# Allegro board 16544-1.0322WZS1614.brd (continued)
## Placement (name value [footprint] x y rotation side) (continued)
C436  SC10U25V5KX-DL-GP  [C805H58]  223.55 64.69 0 top
C440  SC1U10V2KX-L1-GP  [C402H22]  129.79 152.3 270 top
C450  SC10U6D3V3MX-DL-GP  [C603H36]  130.18 206.76 270 top
C451  SCD1U25V2KX-1-DL-GP  [C402H22]  129.03 205.1 180 top
C453  SC4D7U10V3KX-GP  [C603H36]  137.29 197.99 90 top
C454  SC22U6D3V5MX-2DLGP  [C805H54]  133.22 199.64 270 top
C455  SC22U6D3V5MX-2DLGP  [C805H54]  137.54 199.64 90 top
C456  SCD1U50V3KX-DL-GP  [C603H35]  22.87 117.21 0 top
C457  SCD1U25V2KX-1-DL-GP  [C402H22]  21.75 117.33 0 top
C458  SCD1U50V3KX-DL-GP  [C603H35]  33.73 112.93 270 bottom
C459  SC1U50V3KX-1-GP  [C603H36]  25.29 124.53 270 bottom
C460  SC1U6D3V2KX-GP  [C402H22]  209.37 150.27 90 top
C461  SC1U10V2KX-1DLGP  [C402H22]  207.21 143.9 90 top
C462  SCD1U25V2KX-1-DL-GP  [C402H22]  215.77 135.76 90 top
C463  SC1U6D3V2KX-GP  [C402H22]  218.67 136.04 270 top
C464  SC1U6D3V2KX-GP  [C402H22]  228.6 148.59 180 top
C466  SC1U10V2KX-1DLGP  [C402H22]  21.56 137.59 90 bottom
C467  SC1U50V3KX-1-GP  [C603H36]  20.93 139.57 180 bottom
C468  SC10U25V5KX-DL-GP  [C805H58]  88.01 24.43 90 top
C469  SC1U50V3KX-1-GP  [C603H36]  87.63 27.36 90 top
C470  SC10U6D3V3MX-DL-GP  [C603H36]  87.63 26.09 90 top
C471  SCD01U50V2KX-1DLGP  [C402H22]  100.08 82.37 270 top
C472  SCD01U50V2KX-1DLGP  [C402H22]  100.08 83.26 270 top
C473  SCD01U50V2KX-1DLGP  [C402H22]  96.47 86.64 270 top
C474  SCD01U50V2KX-1DLGP  [C402H22]  96.47 87.53 270 top
C475  SC10U25V5KX-DL-GP  [C805H58]  188.98 36.63 270 top
C476  SCD1U25V2KX-1-DL-GP  [C402H22]  189.15 38.05 270 top
C477  SCD1U25V2KX-1-DL-GP  [C402H22]  193.85 62.28 90 top
C478  SCD1U25V2KX-1-DL-GP  [C402H22]  193.85 63.17 90 top
C493  SC10P50V2JN-4DLGP  [C402H22]  184.51 8.46 270 top
C494  SC10P50V2JN-4DLGP  [C402H22]  186.66 8.46 90 top
C495  SCD1U25V2KX-1-DL-GP  [C402H22]  107.09 110.72 270 top
C496  SCD1U25V2KX-1-DL-GP  [C402H22]  107.09 109.83 270 top
C497  SCD1U25V2KX-1-DL-GP  [C402H22]  113.87 90.3 0 top
C498  SC1U10V2KX-1DLGP  [C402H22]  114.83 90.3 0 top
C499  SCD1U25V2KX-1-DL-GP  [C402H22]  97.43 91.59 270 top
C500  SC10U25V5KX-DL-GP  [C805H58]  97.61 90.17 270 top
C501  SCD1U25V2KX-1-DL-GP  [C402H22]  112.75 109.25 270 top
C502  SCD1U25V2KX-1-DL-GP  [C402H22]  112.75 108.36 270 top
C503  SCD1U25V2KX-1-DL-GP  [C402H22]  109.88 106.5 270 top
C504  SCD1U25V2KX-1-DL-GP  [C402H22]  109.88 105.61 270 top
C507  SC1KP50V2KX-1DLGP  [C402H22]  110.11 87.66 90 top
C508  SCD1U25V2KX-1-DL-GP  [C402H22]  103.89 91.16 90 top
C509  SC10U25V5KX-DL-GP  [C805H58]  116.41 90.25 0 top
C510  SCD01U50V2KX-1DLGP  [C402H22]  122.58 98.96 270 bottom
C511  SCD1U25V2KX-1-DL-GP  [C402H22]  122.56 99.87 270 bottom
C512  SC10U6D3V3MX-DL-GP  [C603H36]  122.94 97.92 270 bottom
C513  SCD1U25V2KX-1-DL-GP  [C402H22]  120.68 90.7 180 top
C514  SCD1U25V2KX-1-DL-GP  [C402H22]  119.79 90.7 180 top
C518  SCD1U25V2KX-1-DL-GP  [C402H22]  12.62 136.73 180 top
C521  SCD22U10V2KX-2-GP  [C402H22]  123.85 189.39 270 top
C522  SCD22U10V2KX-2-GP  [C402H22]  123.88 187.05 270 top
C523  SCD22U10V2KX-2-GP  [C402H22]  118.57 176.18 270 bottom
C524  SCD22U10V2KX-2-GP  [C402H22]  123.88 186.14 270 top
C525  SCD22U10V2KX-2-GP  [C402H22]  118.47 183.98 270 top
C526  SCD22U10V2KX-2-GP  [C402H22]  118.47 183.06 270 top
C527  SCD22U10V2KX-2-GP  [C402H22]  123.88 184.92 270 top
C528  SCD22U10V2KX-2-GP  [C402H22]  118.57 179.51 270 bottom
C529  SCD22U10V2KX-2-GP  [C402H22]  118.52 180.85 270 top
C530  SCD22U10V2KX-2-GP  [C402H22]  123.9 182.73 270 top
C531  SCD22U10V2KX-2-GP  [C402H22]  123.83 191.57 270 top
C532  SCD22U10V2KX-2-GP  [C402H22]  118.67 171.43 270 bottom
C533  SCD22U10V2KX-2-GP  [C402H22]  123.83 190.61 270 top
C534  SCD22U10V2KX-2-GP  [C402H22]  118.67 172.39 270 bottom
C535  SCD22U10V2KX-2-GP  [C402H22]  118.47 188.4 270 top
C536  SCD22U10V2KX-2-GP  [C402H22]  123.93 174.78 270 bottom
C537  SCD22U10V2KX-2-GP  [C402H22]  118.47 187.51 270 top
C538  SCD22U10V2KX-2-GP  [C402H22]  123.93 175.7 270 bottom
C539  SCD22U10V2KX-2-GP  [C402H22]  118.57 173.92 270 bottom
C540  SCD22U10V2KX-2-GP  [C402H22]  123.85 188.42 270 top
C541  SCD22U10V2KX-2-GP  [C402H22]  118.57 174.81 270 bottom
C542  SCD22U10V2KX-2-GP  [C402H22]  118.47 186.11 270 top
C543  SCD22U10V2KX-2-GP  [C402H22]  123.93 177.14 270 bottom
C544  SCD22U10V2KX-2-GP  [C402H22]  118.47 185.22 270 top
C545  SCD22U10V2KX-2-GP  [C402H22]  123.93 178.03 270 bottom
C546  SCD22U10V2KX-2-GP  [C402H22]  118.57 177.14 270 bottom
C547  SCD22U10V2KX-2-GP  [C402H22]  123.93 179.43 270 bottom
C548  SCD22U10V2KX-2-GP  [C402H22]  123.93 180.4 270 bottom
C549  SCD22U10V2KX-2-GP  [C402H22]  118.57 178.57 270 bottom
C550  SCD22U10V2KX-2-GP  [C402H22]  123.88 183.98 270 top
C551  SCD22U10V2KX-2-GP  [C402H22]  118.52 181.74 270 top
C552  SCD22U10V2KX-2-GP  [C402H22]  123.9 182.73 270 bottom
C553  SCD22U10V2KX-2-GP  [C402H22]  123.9 181.82 270 bottom
C554  SCD22U10V2KX-2-GP  [C402H22]  118.53 180.85 270 bottom
C555  SCD22U10V2KX-2-GP  [C402H22]  123.9 181.82 270 top
C556  SCD22U10V2KX-2-GP  [C402H22]  118.53 181.74 270 bottom
C557  SCD22U10V2KX-2-GP  [C402H22]  118.57 179.51 270 top
C558  SCD22U10V2KX-2-GP  [C402H22]  123.9 183.98 270 bottom
C559  SCD22U10V2KX-2-GP  [C402H22]  118.57 178.57 270 top
C560  SCD22U10V2KX-2-GP  [C402H22]  123.9 184.92 270 bottom
C561  SCD22U10V2KX-2-GP  [C402H22]  123.93 180.4 270 top
C562  SCD22U10V2KX-2-GP  [C402H22]  118.49 183.98 270 bottom
C563  SCD22U10V2KX-2-GP  [C402H22]  123.93 179.43 270 top
C564  SCD22U10V2KX-2-GP  [C402H22]  118.49 183.06 270 bottom
C565  SCD22U10V2KX-2-GP  [C402H22]  118.57 177.14 270 top
C566  SCD22U10V2KX-2-GP  [C402H22]  123.88 187.05 270 bottom
C567  SCD22U10V2KX-2-GP  [C402H22]  118.57 176.18 270 top
C568  SCD22U10V2KX-2-GP  [C402H22]  123.88 186.14 270 bottom
C569  SCD22U10V2KX-2-GP  [C402H22]  123.77 177.7 270 top
C570  SCD22U10V2KX-2-GP  [C402H22]  118.49 185.22 270 bottom
C571  SCD22U10V2KX-2-GP  [C402H22]  123.77 176.81 270 top
C572  SCD22U10V2KX-2-GP  [C402H22]  118.49 186.11 270 bottom
C573  SCD22U10V2KX-2-GP  [C402H22]  118.57 174.81 270 top
C574  SCD22U10V2KX-2-GP  [C402H22]  123.85 188.42 270 bottom
C575  SCD22U10V2KX-2-GP  [C402H22]  118.57 173.92 270 top
C576  SCD22U10V2KX-2-GP  [C402H22]  123.85 189.39 270 bottom
C577  SCD22U10V2KX-2-GP  [C402H22]  123.77 175.36 270 top
C578  SCD22U10V2KX-2-GP  [C402H22]  118.49 187.51 270 bottom
C579  SCD22U10V2KX-2-GP  [C402H22]  123.77 174.44 270 top
C580  SCD22U10V2KX-2-GP  [C402H22]  118.49 188.4 270 bottom
C581  SCD22U10V2KX-2-GP  [C402H22]  118.67 172.39 270 top
C582  SCD22U10V2KX-2-GP  [C402H22]  123.82 191.57 270 bottom
C583  SCD22U10V2KX-2-GP  [C402H22]  118.67 171.43 270 top
C584  SCD22U10V2KX-2-GP  [C402H22]  123.82 190.61 270 bottom
C592  SCD1U25V2KX-1-DL-GP  [C402H22]  108.23 205.58 90 top
C593  SC10U6D3V3MX-DL-GP  [C603H36]  75.54 165.89 270 bottom
C601  SC1U10V2KX-1DLGP  [C402H22]  73.35 171.85 0 bottom
C602  SC1U10V2KX-1DLGP  [C402H22]  74.74 171.73 270 bottom
C608  SC1U10V2KX-1DLGP  [C402H22]  83.01 174.8 180 bottom
C609  SC1U10V2KX-1DLGP  [C402H22]  82.42 177.01 90 bottom
C610  SC1U10V2KX-1DLGP  [C402H22]  83.08 178.84 0 bottom
C611  SC1U10V2KX-1DLGP  [C402H22]  81.05 172.03 90 bottom
C616  SCD1U25V2KX-1-DL-GP  [C402H22]  83.09 170.31 180 bottom
C617  SC1U10V2KX-1DLGP  [C402H22]  83.01 172.82 180 bottom
C618  SC1U10V2KX-1DLGP  [C402H22]  80.47 180.11 180 bottom
C619  SC10U6D3V3MX-DL-GP  [C603H36]  82.25 181 270 bottom
C622  SC10U6D3V3MX-DL-GP  [C603H36]  77.26 172.68 90 bottom
C630  SC1U10V2KX-1DLGP  [C402H22]  116.03 159.08 0 top
C631  SC1U10V2KX-1DLGP  [C402H22]  100.25 213.75 90 top
C632  SC1U10V2KX-1DLGP  [C402H22]  100.66 213.77 90 bottom
C634  SC1U10V2KX-1DLGP  [C402H22]  75.58 169.04 0 bottom
C637  SCD1U25V2KX-1-DL-GP  [C402H22]  125.89 165.86 180 top
C638  SC10U6D3V3MX-DL-GP  [C603H36]  99.59 149.21 0 top
C639  SC2D2U10V3KX-1DLGP-U  [C603H36]  100.84 149.21 0 top
C640  SC15P50V2JN-DL-GP  [C402H22]  101.52 152.08 0 top
C641  SC15P50V2JN-DL-GP  [C402H22]  101.53 154.04 180 top
C653  SCD01U50V2KX-1DLGP  [C402H22]  118.92 125.2 90 top
C656  SC1U10V2KX-1DLGP  [C402H22]  65.06 175.57 0 bottom
C657  SC1U10V2KX-1DLGP  [C402H22]  65.94 175.58 0 bottom
C658  SC1U10V2KX-1DLGP  [C402H22]  68.12 185.54 90 bottom
C659  SC1U10V2KX-1DLGP  [C402H22]  68.11 176.01 90 bottom
C660  SC1U10V2KX-1DLGP  [C402H22]  77.99 148.4 90 bottom
C661  SC1U10V2KX-1DLGP  [C402H22]  78.02 149.29 90 bottom
C662  SC1U10V2KX-1DLGP  [C402H22]  78.02 150.16 90 bottom
C663  SC22U6D3V3MX-1-DL-GP  [C603H40]  72.03 180.1 90 bottom
C664  SC22U6D3V3MX-1-DL-GP  [C603H40]  72.03 181.37 90 bottom
C665  SC22U6D3V3MX-1-DL-GP  [C603H40]  72.03 182.64 90 bottom
C666  SC22U6D3V3MX-1-DL-GP  [C603H40]  72.03 184.04 90 bottom
C667  SC22U6D3V3MX-1-DL-GP  [C603H40]  72.03 185.31 90 bottom
C668  SC1U10V2KX-1DLGP  [C402H22]  119.13 225.93 180 top
C669  SC1U10V2KX-1DLGP  [C402H22]  118.24 225.93 180 top
C670  SC1U10V2KX-1DLGP  [C402H22]  65.05 183.51 0 bottom
C671  SC1U10V2KX-1DLGP  [C402H22]  65.92 183.5 0 bottom
C672  SC1U10V2KX-1DLGP  [C402H22]  65.06 181.55 180 bottom
C673  SC1U10V2KX-1DLGP  [C402H22]  65.07 179.49 0 bottom
C674  SC1U10V2KX-1DLGP  [C402H22]  65.94 179.49 0 bottom
C675  SC1U10V2KX-1DLGP  [C402H22]  65.06 177.49 180 bottom
C676  SC22U6D3V3MX-1-DL-GP  [C603H40]  70.85 172.68 270 bottom
C677  SC22U6D3V3MX-1-DL-GP  [C603H40]  68.12 174.62 90 bottom
C678  SC22U6D3V3MX-1-DL-GP  [C603H40]  72.03 174.96 90 bottom
C679  SC22U6D3V3MX-1-DL-GP  [C603H40]  72.03 176.29 90 bottom
C680  SC22U6D3V3MX-1-DL-GP  [C603H40]  72.03 177.56 90 bottom
C681  SC22U6D3V3MX-1-DL-GP  [C603H40]  72.03 178.83 90 bottom
C682  SC22U6D3V3MX-1-DL-GP  [C603H40]  77.37 175.81 0 bottom
C683  SC1U10V2KX-1DLGP  [C402H22]  89.85 200.89 90 bottom
C684  SC1U10V2KX-1DLGP  [C402H22]  74.77 172.66 270 bottom
C685  SC1U10V2KX-1DLGP  [C402H22]  52.03 196.69 270 bottom
C686  SC1U10V2KX-1DLGP  [C402H22]  65.05 185.42 180 bottom
C687  SC22U6D3V3MX-1-DL-GP  [C603H40]  77.34 180.42 0 bottom
C688  SC1U10V2KX-1DLGP  [C402H22]  65.92 185.42 180 bottom
C689  SC1U10V2KX-1DLGP  [C402H22]  65.92 181.55 180 bottom
C690  SC1U10V2KX-1DLGP  [C402H22]  65.93 177.49 180 bottom
C691  SC1U10V2KX-1DLGP  [C402H22]  68.11 184.67 90 bottom
C692  SC1U10V2KX-1DLGP  [C402H22]  68.11 183.79 90 bottom
C693  SC22U6D3V3MX-1-DL-GP  [C603H40]  75.43 176.17 0 bottom
C694  SC22U6D3V3MX-1-DL-GP  [C603H40]  75.46 182.52 0 bottom
C695  SC22U6D3V3MX-1-DL-GP  [C603H40]  75.47 185.21 0 bottom
C696  SC1U10V2KX-1DLGP  [C402H22]  61.06 174.05 180 bottom
C697  SC1U10V2KX-1DLGP  [C402H22]  53.54 193.23 180 bottom
C698  SC1U10V2KX-1DLGP  [C402H22]  58.47 192.06 180 bottom
C699  SC1U10V2KX-1DLGP  [C402H22]  54.04 197.51 90 bottom
C700  SC1U10V2KX-1DLGP  [C402H22]  66.12 172.46 90 bottom
C701  SC1U10V2KX-1DLGP  [C402H22]  62.87 171.58 270 bottom
C702  SC1U10V2KX-1DLGP  [C402H22]  77.19 183.41 180 bottom
C703  SC1U10V2KX-1DLGP  [C402H22]  77.09 184.81 270 bottom
C704  SC1U10V2KX-1DLGP  [C402H22]  68.11 182.92 90 bottom
C705  SC1U10V2KX-1DLGP  [C402H22]  68.11 182.06 90 bottom
C706  SC1U10V2KX-1DLGP  [C402H22]  68.11 181.19 90 bottom
C707  SC1U10V2KX-1DLGP  [C402H22]  68.11 180.33 90 bottom
C708  SC1U10V2KX-1DLGP  [C402H22]  60.93 171.54 180 bottom
C709  SC1U10V2KX-1DLGP  [C402H22]  76.01 189.1 90 bottom
C710  SC1U10V2KX-1DLGP  [C402H22]  78.49 183.55 0 bottom
C711  SC1U10V2KX-1DLGP  [C402H22]  44.34 156.47 180 bottom
C712  SC1U10V2KX-1DLGP  [C402H22]  46.17 156.47 180 bottom
C713  SC1U10V2KX-1DLGP  [C402H22]  54.04 198.42 90 bottom
C714  SC1U10V2KX-1DLGP  [C402H22]  89.85 199.94 90 bottom
C715  SC1U10V2KX-1DLGP  [C402H22]  54.04 196.55 90 bottom
C716  SC1U10V2KX-1DLGP  [C402H22]  71.49 187.47 270 bottom
C717  SC1U10V2KX-1DLGP  [C402H22]  63.65 187.33 270 bottom
C718  SC1U10V2KX-1DLGP  [C402H22]  64.19 172.7 270 bottom
C719  SC1U10V2KX-1DLGP  [C402H22]  79.04 174.03 180 bottom
C720  SC1U10V2KX-1DLGP  [C402H22]  77.31 178.11 180 bottom
C721  SC1U10V2KX-1DLGP  [C402H22]  68.11 179.47 90 bottom
C722  SC1U10V2KX-1DLGP  [C402H22]  52.63 193.26 180 bottom
C723  SC22U6D3V3MX-1-DL-GP  [C603H40]  73.84 187.32 270 bottom
C724  SC22U6D3V3MX-1-DL-GP  [C603H40]  60.87 180.13 90 bottom
C725  SC22U6D3V3MX-1-DL-GP  [C603H40]  62.63 173.36 0 bottom
C726  SC22U6D3V3MX-1-DL-GP  [C603H40]  69.9 188.65 0 bottom
C727  SC10U6D3V3MX-DL-GP  [C603H36]  121.42 217.12 90 top
C728  SC1U10V2KX-1DLGP  [C402H22]  68.11 178.6 90 bottom
C729  SC1U10V2KX-1DLGP  [C402H22]  68.11 177.74 90 bottom
C730  SC1U10V2KX-1DLGP  [C402H22]  51.98 199.16 270 bottom
C731  SC1U10V2KX-1DLGP  [C402H22]  52.04 197.59 270 bottom
C732  SC1U10V2KX-1DLGP  [C402H22]  68.11 176.88 90 bottom
C733  SC1U10V2KX-1DLGP  [C402H22]  89.83 199.02 90 bottom
C734  SC1U10V2KX-1DLGP  [C402H22]  45.3 156.47 180 bottom
C735  SC1U10V2KX-1DLGP  [C402H22]  78.35 189.03 270 bottom
C736  SC1U10V2KX-1DLGP  [C402H22]  66.29 187.29 90 bottom
C737  SC120P50V2JN-1-DL-GP  [C402H22]  43.87 207.92 90 top
C738  SC1U10V2KX-1DLGP  [C402H22]  62.74 179.5 180 bottom
C739  SC1U10V2KX-1DLGP  [C402H22]  62.62 177.57 0 bottom
C740  SC120P50V2JN-1-DL-GP  [C402H22]  49.3 159.14 270 bottom
C741  SC1U10V2KX-1DLGP  [C402H22]  79.34 222.43 270 bottom
C742  SC1U10V2KX-1DLGP  [C402H22]  43.62 223.7 270 bottom
C743  SC1U10V2KX-1DLGP  [C402H22]  27.85 169.37 90 bottom
C750  SCD1U25V2KX-1-DL-GP  [C402H22]  93.47 222.95 0 bottom
C751  SCD1U25V2KX-1-DL-GP  [C402H22]  94.8 214.89 0 bottom
C752  SCD1U25V2KX-1-DL-GP  [C402H22]  94.8 217.09 180 bottom
C753  SCD1U25V2KX-1-DL-GP  [C402H22]  93.6 226.95 0 bottom
C754  SCD1U25V2KX-1-DL-GP  [C402H22]  93.6 224.95 0 bottom
C755  SCD1U25V2KX-1-DL-GP  [C402H22]  82.2 217.45 180 bottom
C756  SCD1U25V2KX-1-DL-GP  [C402H22]  82.2 213.45 180 bottom
C757  SCD1U25V2KX-1-DL-GP  [C402H22]  90.83 224.01 180 bottom
C758  SC1U10V2KX-1DLGP  [C402H22]  83.42 225.51 180 bottom
C759  SC1U10V2KX-1DLGP  [C402H22]  86.2 224.15 0 bottom
C760  SC1U10V2KX-1DLGP  [C402H22]  82.2 215.45 180 bottom
C761  SC1U10V2KX-1DLGP  [C402H22]  84.8 226.53 270 bottom
C762  SC1U10V2KX-1DLGP  [C402H22]  87.68 225.01 0 bottom
C763  SC1U10V2KX-1DLGP  [C402H22]  86.2 226.25 0 bottom
C764  SC1U10V2KX-1DLGP  [C402H22]  91.81 223.65 0 bottom
C765  SC10U6D3V3MX-DL-GP  [C603H36]  88.9 227.23 270 bottom
C767  SCD1U25V2KX-1-DL-GP  [C402H22]  75.03 223.08 0 bottom
C768  SCD1U25V2KX-1-DL-GP  [C402H22]  75.04 225.11 0 bottom
C769  SCD1U25V2KX-1-DL-GP  [C402H22]  76.5 226.85 0 bottom
C770  SCD1U25V2KX-1-DL-GP  [C402H22]  71.12 225.28 90 bottom
C771  SCD1U25V2KX-1-DL-GP  [C402H22]  66.35 226.4 270 bottom
C772  SCD1U25V2KX-1-DL-GP  [C402H22]  76.28 215.67 180 bottom
C773  SCD1U25V2KX-1-DL-GP  [C402H22]  76.28 213.61 180 bottom
C774  SCD1U25V2KX-1-DL-GP  [C402H22]  74.15 224.53 0 bottom
C775  SC1U10V2KX-1DLGP  [C402H22]  67.35 222.4 270 bottom
C776  SC1U10V2KX-1DLGP  [C402H22]  72.65 223.3 270 bottom
C777  SC1U10V2KX-1DLGP  [C402H22]  76.58 224.85 0 bottom
C778  SC1U10V2KX-1DLGP  [C402H22]  64.75 222.5 270 bottom
C779  SC1U10V2KX-1DLGP  [C402H22]  73.65 226.4 90 bottom
C780  SC1U10V2KX-1DLGP  [C402H22]  63.7 217.25 180 bottom
C781  SC1U10V2KX-1DLGP  [C402H22]  63.7 215.13 0 bottom
C782  SC10U6D3V3MX-DL-GP  [C603H36]  70.4 227 90 bottom
C784  SCD1U25V2KX-1-DL-GP  [C402H22]  45.21 215.46 180 bottom
C785  SCD1U25V2KX-1-DL-GP  [C402H22]  45.12 217.45 180 bottom
C786  SCD1U25V2KX-1-DL-GP  [C402H22]  46.43 226.7 0 bottom
C787  SCD1U25V2KX-1-DL-GP  [C402H22]  55.15 226.4 90 bottom
C788  SCD1U25V2KX-1-DL-GP  [C402H22]  54.8 223.65 0 bottom
C789  SCD1U25V2KX-1-DL-GP  [C402H22]  57.8 215.25 180 bottom
C790  SCD1U25V2KX-1-DL-GP  [C402H22]  49.2 226.25 0 bottom
C791  SCD1U25V2KX-1-DL-GP  [C402H22]  56.6 226.95 0 bottom
C792  SC1U10V2KX-1DLGP  [C402H22]  56.6 224.95 0 bottom
C793  SC1U10V2KX-1DLGP  [C402H22]  56.39 222.95 0 bottom
C794  SC1U10V2KX-1DLGP  [C402H22]  49.2 224.15 0 bottom
C795  SC1U10V2KX-1DLGP  [C402H22]  47.82 224.16 90 bottom
C796  SC1U10V2KX-1DLGP  [C402H22]  46.4 224.7 0 bottom
C797  SC1U10V2KX-1DLGP  [C402H22]  47.82 226.44 270 bottom
C798  SC1U10V2KX-1DLGP  [C402H22]  53.22 225.26 180 bottom
C799  SC10U6D3V3MX-DL-GP  [C603H36]  51.85 227 270 bottom
C801  SCD1U25V2KX-1-DL-GP  [C402H22]  25.05 193.4 90 bottom
C802  SCD1U25V2KX-1-DL-GP  [C402H22]  26.99 193.42 90 bottom
C803  SCD1U25V2KX-1-DL-GP  [C402H22]  26.35 195.2 90 bottom
C804  SCD1U25V2KX-1-DL-GP  [C402H22]  23.05 193.4 90 bottom
C805  SCD1U25V2KX-1-DL-GP  [C402H22]  27.14 196.1 270 bottom
C806  SCD1U25V2KX-1-DL-GP  [C402H22]  34.6 192.15 270 bottom
C807  SCD1U25V2KX-1-DL-GP  [C402H22]  32.65 192.2 270 bottom
C808  SCD1U25V2KX-1-DL-GP  [C402H22]  24.59 197.48 0 bottom
C809  SC1U10V2KX-1DLGP  [C402H22]  24.93 200.83 270 bottom
C810  SC1U10V2KX-1DLGP  [C402H22]  34.55 204.85 270 bottom
C811  SC1U10V2KX-1DLGP  [C402H22]  32.55 204.8 270 bottom
C812  SC1U10V2KX-1DLGP  [C402H22]  22.95 200.8 270 bottom
C813  SC1U10V2KX-1DLGP  [C402H22]  23.52 202.2 180 bottom
C814  SC1U10V2KX-1DLGP  [C402H22]  23.15 203.6 90 bottom
C815  SC1U10V2KX-1DLGP  [C402H22]  26.18 205.26 270 bottom
C816  SC10U6D3V3MX-DL-GP  [C603H36]  23 198.15 180 bottom
C818  SC1U10V2KX-1DLGP  [C402H22]  62.48 145.87 180 bottom
C821  SC1U10V2KX-1DLGP  [C402H22]  104.08 187.45 90 bottom
C822  SC1U10V2KX-1DLGP  [C402H22]  80.86 222.28 180 bottom
C823  SC1U10V2KX-1DLGP  [C402H22]  25.82 202.22 0 bottom
C830  SC10U6D3V3MX-DL-GP  [C603H36]  68.77 224.84 90 bottom
C831  SC10U6D3V3MX-DL-GP  [C603H36]  95.27 222.7 0 bottom
C832  SC10U6D3V3MX-DL-GP  [C603H36]  56.39 141.13 180 bottom
C833  SC10U6D3V3MX-DL-GP  [C603H36]  58.19 223.92 0 bottom
C834  SC10U6D3V3MX-DL-GP  [C603H36]  38.13 211.49 180 bottom
C835  SC10U6D3V3MX-DL-GP  [C603H36]  38.81 222.68 180 top
C836  SC10U6D3V3MX-DL-GP  [C603H36]  25 179.65 180 bottom
C837  SC22U10V3MX-1-GP  [C603H42]  40.06 222.68 180 top
C838  SC22U10V3MX-1-GP  [C603H42]  109 193.6 0 bottom
C839  SC22U10V3MX-1-GP  [C603H42]  106.9 193.74 180 bottom
C840  SCD1U25V2KX-1-DL-GP  [C402H22]  23.6 176.35 0 bottom
C841  SCD1U25V2KX-1-DL-GP  [C402H22]  25.55 176 90 bottom
C842  SCD1U25V2KX-1-DL-GP  [C402H22]  26.73 177.4 180 bottom
C843  SCD1U25V2KX-1-DL-GP  [C402H22]  23.47 173.5 90 bottom
C844  SCD1U25V2KX-1-DL-GP  [C402H22]  25.47 173.5 90 bottom
C845  SCD1U25V2KX-1-DL-GP  [C402H22]  32.35 173.7 270 bottom
C846  SCD1U25V2KX-1-DL-GP  [C402H22]  34.33 173.67 270 bottom
C847  SCD1U25V2KX-1-DL-GP  [C402H22]  36.39 173.72 270 bottom
C848  SC1U10V2KX-1DLGP  [C402H22]  23.35 185.1 90 bottom
C849  SC1U10V2KX-1DLGP  [C402H22]  27.5 185.25 180 bottom
C850  SC1U10V2KX-1DLGP  [C402H22]  32.75 186.38 270 bottom
C851  SC1U10V2KX-1DLGP  [C402H22]  34.96 186.36 90 bottom
C852  SC1U10V2KX-1DLGP  [C402H22]  25.9 183.55 0 bottom
C853  SC1U10V2KX-1DLGP  [C402H22]  23.57 183.7 180 bottom
C854  SC1U10V2KX-1DLGP  [C402H22]  24.15 182.27 90 bottom
C855  SC10U6D3V3MX-DL-GP  [C603H36]  23 179.35 0 bottom
C857  SCD1U25V2KX-1-DL-GP  [C402H22]  36.2 156.14 180 bottom
C858  SCD1U25V2KX-1-DL-GP  [C402H22]  23.6 165.35 180 bottom
C859  SCD1U25V2KX-1-DL-GP  [C402H22]  25.91 165.29 0 bottom
C860  SCD1U25V2KX-1-DL-GP  [C402H22]  25.85 163.8 90 bottom
C861  SCD1U25V2KX-1-DL-GP  [C402H22]  23.6 157.85 0 bottom
C862  SCD1U25V2KX-1-DL-GP  [C402H22]  26.95 159.25 270 bottom
C863  SCD1U25V2KX-1-DL-GP  [C402H22]  26.35 158.2 90 bottom
C864  SCD1U25V2KX-1-DL-GP  [C402H22]  34.71 155.2 270 bottom
C865  SC1U10V2KX-1DLGP  [C402H22]  32.61 155.2 270 bottom
C866  SC1U10V2KX-1DLGP  [C402H22]  36.55 167.8 270 bottom
C867  SC1U10V2KX-1DLGP  [C402H22]  23.05 156.4 90 bottom
C868  SC1U10V2KX-1DLGP  [C402H22]  25.05 156.4 90 bottom
C869  SC1U10V2KX-1DLGP  [C402H22]  26.99 156.46 90 bottom
C870  SC1U10V2KX-1DLGP  [C402H22]  32.6 167.95 270 bottom
C871  SC1U10V2KX-1DLGP  [C402H22]  34.55 167.8 270 bottom
C872  SC10U6D3V3MX-DL-GP  [C603H36]  25.1 160.82 0 bottom
C874  SCD1U25V2KX-1-DL-GP  [C402H22]  52.35 141.6 270 bottom
C875  SCD1U25V2KX-1-DL-GP  [C402H22]  57.49 141.51 180 bottom
C876  SCD1U25V2KX-1-DL-GP  [C402H22]  59.65 141.6 90 bottom
C877  SCD1U25V2KX-1-DL-GP  [C402H22]  50.9 143.35 180 bottom
C878  SCD1U25V2KX-1-DL-GP  [C402H22]  61.08 141.22 180 bottom
C879  SCD1U25V2KX-1-DL-GP  [C402H22]  50.9 141.35 180 bottom
C880  SCD1U25V2KX-1-DL-GP  [C402H22]  52.45 143.9 90 bottom
C881  SCD1U25V2KX-1-DL-GP  [C402H22]  53.35 145.6 270 bottom
C882  SC1U10V2KX-1DLGP  [C402H22]  49.73 150.95 0 bottom
C883  SC1U10V2KX-1DLGP  [C402H22]  49.73 153.05 180 bottom
C884  SC1U10V2KX-1DLGP  [C402H22]  50.75 145.5 270 bottom
C885  SC1U10V2KX-1DLGP  [C402H22]  58.65 144.7 270 bottom
C886  SC1U10V2KX-1DLGP  [C402H22]  62.5 150.35 0 bottom
C887  SC1U10V2KX-1DLGP  [C402H22]  62.5 152.35 0 bottom
C888  SC1U10V2KX-1DLGP  [C402H22]  62.5 154.35 0 bottom
C889  SC10U6D3V3MX-DL-GP  [C603H36]  56.35 143.1 270 bottom
C891  SCD1U25V2KX-1-DL-GP  [C402H22]  99.65 187.5 90 bottom
C892  SCD1U25V2KX-1-DL-GP  [C402H22]  96.95 200.3 270 bottom
C893  SCD1U25V2KX-1-DL-GP  [C402H22]  108.14 188.98 90 bottom
C894  SCD1U25V2KX-1-DL-GP  [C402H22]  97.65 187.5 90 bottom
C895  SCD1U25V2KX-1-DL-GP  [C402H22]  108.4 197.65 180 bottom
C896  SCD1U25V2KX-1-DL-GP  [C402H22]  105.3 191.45 180 bottom
C897  SCD1U25V2KX-1-DL-GP  [C402H22]  106.54 190.04 270 bottom
C898  SCD1U25V2KX-1-DL-GP  [C402H22]  106.57 196.14 270 bottom
C899  SC1U10V2KX-1DLGP  [C402H22]  108.65 199.1 270 bottom
C900  SC1U10V2KX-1DLGP  [C402H22]  104.4 196.65 180 bottom
C901  SC1U10V2KX-1DLGP  [C402H22]  108.41 190.39 0 bottom
C902  SC1U10V2KX-1DLGP  [C402H22]  99.05 200.3 90 bottom
C903  SC1U10V2KX-1DLGP  [C402H22]  95.65 187.5 90 bottom
C904  SC1U10V2KX-1DLGP  [C402H22]  106.1 197.55 0 bottom
C905  SC1U10V2KX-1DLGP  [C402H22]  104.5 199.25 180 bottom
C906  SC10U6D3V3MX-DL-GP  [C603H36]  106.12 200.84 270 bottom
C908  SC1U10V2KX-1DLGP  [C402H22]  27.85 172.5 270 bottom
C911  SCD1U25V2KX-1-DL-GP  [C402H22]  13.44 165.05 270 top
C912  SCD1U25V2KX-1-DL-GP  [C402H22]  13.44 164.13 270 top
C913  SCD1U25V2KX-1-DL-GP  [C402H22]  17 162.84 270 top
C914  SCD1U25V2KX-1-DL-GP  [C402H22]  17 161.79 270 top
C915  SCD1U25V2KX-1-DL-GP  [C402H22]  13.44 160.88 270 top
C916  SCD1U25V2KX-1-DL-GP  [C402H22]  13.44 159.84 270 top
C917  SCD1U25V2KX-1-DL-GP  [C402H22]  17.05 158.87 270 top
C918  SCD1U25V2KX-1-DL-GP  [C402H22]  17.05 157.96 270 top
C919  SCD1U25V2KX-1-DL-GP  [C402H22]  13.44 145.51 270 top
C920  SCD1U25V2KX-1-DL-GP  [C402H22]  13.44 146.43 270 top
C921  SCD1U25V2KX-1-DL-GP  [C402H22]  17.28 147.47 270 top
C922  SCD1U25V2KX-1-DL-GP  [C402H22]  17.28 148.38 270 top
C923  SCD1U25V2KX-1-DL-GP  [C402H22]  13.44 149.68 270 top
C924  SCD1U25V2KX-1-DL-GP  [C402H22]  13.44 150.59 270 top
C925  SCD01U50V2KX-1DLGP  [C402H22]  195.47 172.08 90 top
C926  SC150P50V2JN-3DLGP  [C402H22]  117.35 117.98 90 top
C929  SC1U10V2KX-1DLGP  [C402H22]  141.55 13.72 90 top
C931  SC1KP50V2KX-1DLGP  [C402H22]  134.37 12.7 270 top
C932  SC10U10V5KX-2DLGP  [C805H50]  133.88 12.45 90 bottom
C934  SCD1U25V2KX-1-DL-GP  [C402H22]  132.21 11 90 bottom
C947  SCD01U50V2KX-1DLGP  [C402H22]  128.65 164.97 270 top
C948  SCD1U25V2KX-1-DL-GP  [C402H22]  130.3 160.15 180 top
C952  SCD1U25V2KX-1-DL-GP  [C402H22]  99.16 204.88 180 top
C953  SCD1U25V2KX-1-DL-GP  [C402H22]  17.22 152.31 270 top
C954  SCD1U25V2KX-1-DL-GP  [C402H22]  17.22 153.28 270 top
C955  SCD1U25V2KX-1-DL-GP  [C402H22]  13.43 153.89 270 top
C956  SCD1U25V2KX-1-DL-GP  [C402H22]  13.43 154.93 270 top
C961  SC10U25V5KX-DL-GP  [C805H58]  170.84 7.01 180 bottom
C962  SC10U25V5KX-DL-GP  [C805H58]  172.91 6.33 180 bottom
C963  SCD1U25V2KX-1-DL-GP  [C402H22]  169.29 7.24 180 bottom
C964  SC10U25V5KX-DL-GP  [C805H58]  176.28 3.8 90 top
C965  SC10U25V5KX-DL-GP  [C805H58]  173.55 5.73 270 top
C966  SCD1U25V2KX-1-DL-GP  [C402H22]  173.34 4.08 270 top
C970  SC1U10V2KX-1DLGP  [C402H22]  125.22 200.79 90 top
C971  SCD1U25V2KX-1-DL-GP  [C402H22]  123.19 196.6 0 top
C974  SC10U10V5KX-2DLGP  [C805H50]  130.81 199.43 270 bottom
C975  SCD1U25V2KX-1-DL-GP  [C402H22]  129.92 199.64 90 top
C976  SC1U10V2KX-1DLGP  [C402H22]  143.38 42.42 90 bottom
C977  SCD1U25V2KX-1-DL-GP  [C402H22]  144.04 41.48 90 bottom
C979  SC1KP50V2KX-1DLGP  [C402H22]  142.7 40.41 270 bottom
C980  SC10U10V5KX-2DLGP  [C805H50]  134.11 16.71 0 bottom
C981  SCD1U25V2KX-1-DL-GP  [C402H22]  132.59 17.14 0 bottom
C982  SC10U10V5KX-2DLGP  [C805H50]  207.72 28.3 0 bottom
C983  SCD1U25V2KX-1-DL-GP  [C402H22]  209.17 26.57 180 bottom
C984  SCD1U25V2KX-1-DL-GP  [C402H22]  117 69 180 top
C985  SCD1U25V2KX-1-DL-GP  [C402H22]  116.01 69 180 top
C986  SCD1U25V2KX-1-DL-GP  [C402H22]  114.47 68.47 90 top
C987  SCD1U25V2KX-1-DL-GP  [C402H22]  114.47 69.34 90 top
C988  SCD1U25V2KX-1-DL-GP  [C402H22]  12.47 136.78 0 bottom
C989  SC1U10V2KX-1DLGP  [C402H22]  138.05 17.4 270 top
C990  SC1U10V2KX-1DLGP  [C402H22]  144.65 39.5 90 bottom
C991  SC1KP50V2KX-1DLGP  [C402H22]  134.49 14.78 270 top
C996  SC1U10V2KX-1DLGP  [C402H22]  147.07 37.69 90 top
C997  SCD1U25V2KX-1-DL-GP  [C402H22]  146.35 39.88 90 top
C999  SC1KP50V2KX-1DLGP  [C402H22]  142.75 39.5 270 bottom
C1000  SC10U10V5KX-2DLGP  [C805H50]  136.17 39.75 270 top
C1001  SCD1U25V2KX-1-DL-GP  [C402H22]  136.14 41.27 270 top
C1004  SCD1U10V2KX-5GP  [C402H22]  119.04 64.51 0 top
C1005  SC1U10V2KX-1DLGP  [C402H22]  107.76 41.72 0 top
C1006  SCD1U10V2KX-5DLGP  [C402H22]  102.55 58.13 270 bottom
C1009  SCD1U25V2KX-1-DL-GP  [C402H22]  122.26 65.44 90 top
C1010  SC2D2U10V3KX-1DLGP-U  [C603H36]  97.61 59.72 270 top
C1011  SC33P50V2JN-3DLGP  [C402H22]  97.21 50.47 90 bottom
C1016  SCD1U10V2KX-5GP  [C402H22]  122.27 63.36 270 top
C1017  SCD1U25V2KX-1-DL-GP  [C402H22]  119.56 58.6 180 bottom
C1020  SC220P50V2KX-3GP  [C402H22]  102.44 56.95 270 bottom
C1042  SCD1U25V2KX-1-DL-GP  [C402H22]  185.43 127.3 0 top
C1043  SCD1U25V2KX-1-DL-GP  [C402H22]  222.2 51.71 180 top
C1044  SC10U25V5KX-DL-GP  [C805H58]  225.63 51.69 0 top
C1045  SC10U25V5KX-DL-GP  [C805H58]  223.67 51.69 0 top
C1073  SC10U6D3V2MX-2-GP  [C402-TO0D2H28]  150.93 162.61 90 bottom
C1074  SCD22U10V2KX-2-GP  [C402H22]  152.15 165.48 270 bottom
C1081  SCD22U10V2KX-2-GP  [C402H22]  143.53 169.58 0 bottom
C1108  SC1U10V2KX-1DLGP  [C402H22]  89.32 225.56 90 bottom
C1109  SC1U10V2KX-1DLGP  [C402H22]  76.3 217.65 180 bottom
C1110  SC1U10V2KX-1DLGP  [C402H22]  53.73 223.35 180 bottom
C1111  SC1U10V2KX-1DLGP  [C402H22]  23.6 194.85 0 bottom
C1112  SC1U10V2KX-1DLGP  [C402H22]  26.16 182.17 270 bottom
C1113  SC1U10V2KX-1DLGP  [C402H22]  25.52 168 90 bottom
C1114  SC1U10V2KX-1DLGP  [C402H22]  61.08 143.22 180 bottom
C1115  SC1U10V2KX-1DLGP  [C402H22]  106.65 199.1 270 bottom
C1116  SCD1U50V3KX-DL-GP  [C603H35]  191.34 36.02 180 top
C1117  SCD1U50V3KX-DL-GP  [C603H35]  185.8 29.97 90 top
C1121  SC2200P50V2KX-2DLGP  [C402H22]  110.16 51.84 0 bottom
C1122  SCD1U25V2KX-1-DL-GP  [C402H22]  198.01 53.69 90 top
C1123  SCD01U50V2KX-1DLGP  [C402H22]  210.13 62.99 0 top
C1124  SCD1U16V2ZY-2DLGP  [C402H22]  208.36 58.27 180 top
C1125  SCD1U25V2KX-1-DL-GP  [C402H22]  89.16 81.17 90 top
C1126  SCD1U25V2KX-1-DL-GP  [C402H22]  89.15 80.26 90 top
C1127  SCD1U25V2KX-1-DL-GP  [C402H22]  89.15 78.99 90 top
C1128  SCD1U25V2KX-1-DL-GP  [C402H22]  89.15 78.11 90 top
C1129  SCD1U25V2KX-1-DL-GP  [C402H22]  89.15 76.83 90 top
C1130  SCD1U25V2KX-1-DL-GP  [C402H22]  89.15 75.95 90 top
C1131  SCD1U25V2KX-1-DL-GP  [C402H22]  89.15 74.68 90 top
C1132  SCD1U25V2KX-1-DL-GP  [C402H22]  89.13 73.79 90 top
C1133  SCD1U25V2KX-1-DL-GP  [C402H22]  88.8 58.97 90 top
C1134  SCD1U25V2KX-1-DL-GP  [C402H22]  88.8 59.89 90 top
C1135  SCD1U25V2KX-1-DL-GP  [C402H22]  88.73 61.66 90 top
C1136  SCD1U25V2KX-1-DL-GP  [C402H22]  88.73 62.55 90 top
C1137  SCD1U25V2KX-1-DL-GP  [C402H22]  88.83 64.46 90 top
C1138  SCD1U25V2KX-1-DL-GP  [C402H22]  88.83 65.4 90 top
C1139  SCD1U25V2KX-1-DL-GP  [C402H22]  88.8 67.15 90 top
C1140  SCD1U25V2KX-1-DL-GP  [C402H22]  88.8 68.06 90 top
C1141  SC10U25V5KX-DL-GP  [C805H58]  188.67 10.9 270 bottom
C1142  SC10U25V5KX-DL-GP  [C805H58]  188.67 8.86 270 bottom
C1143  SCD1U25V2KX-1-DL-GP  [C402H22]  186 7.34 270 bottom
C1144  SCD1U25V2KX-1-DL-GP  [C402H22]  181.1 17.63 270 top
C1145  SC1KP50V2KX-1DLGP  [C402H22]  186.41 18.47 180 top
C1146  SCD1U10V2KX-5GP  [C402H22]  125.35 61.04 270 top
C1149  SCD1U25V2KX-1-DL-GP  [C402H22]  124.76 90.5 180 top
C1150  SCD1U25V2KX-1-DL-GP  [C402H22]  123.88 90.5 180 top
C1151  SC470P50V2KX-3DLGP  [C402H22]  197.79 37.41 90 bottom
C1152  SCD1U25V2KX-1-DL-GP  [C402H22]  161.5 219.84 90 top
C1153  SCD1U25V2KX-1-DL-GP  [C402H22]  171.37 219.99 270 top
C1154  SCD1U25V2KX-1-DL-GP  [C402H22]  187.24 220.01 270 top
C1155  SCD1U25V2KX-1-DL-GP  [C402H22]  219.79 192.89 90 top
C1156  SCD1U25V2KX-1-DL-GP  [C402H22]  229.06 198.4 90 top
C1157  SCD1U25V2KX-1-DL-GP  [C402H22]  72.49 115.5 180 top
C1158  SCD1U25V2KX-1-DL-GP  [C402H22]  59.25 113.79 270 top
C1159  SCD1U25V2KX-1-DL-GP  [C402H22]  90.37 113.56 90 top
C1160  SCD1U25V2KX-1-DL-GP  [C402H22]  125.3 45.87 90 top
C2509  SC3D9P50V2CN-1GP  [C402H22]  107.59 77.17 180 top
C2510  SC4D7P50V2CN-1GP  [C402H22]  107.67 74.21 0 top
C2511  SC1U10V2KX-1DLGP  [C402H22]  116.23 77.42 270 top
C2512  SC100P50V2JN-3DLGP  [C402H22]  214 153.03 270 bottom
C2513  SC10U6D3V3MX-DL-GP  [C603H36]  209.55 151.76 90 bottom
C2514  SCD01U50V2KX-1DLGP  [C402H22]  127.2 130.7 0 top
C2515  SCD1U25V2KX-1-DL-GP  [C402H22]  98.91 147.35 90 top
C2516  SC100P50V2JN-3DLGP  [C402H22]  129.01 117.4 90 top
C2517  SC10U6D3V3MX-DL-GP  [C603H36]  120.8 119.91 270 top
C2520  SCD1U25V2KX-1-DL-GP  [C402H22]  221.62 230.38 90 top
C2521  SCD1U25V2KX-1-DL-GP  [C402H22]  18.11 225.68 0 top
C2522  SCD1U25V2KX-1-DL-GP  [C402H22]  14.48 183.13 90 top
C2523  SCD1U25V2KX-1-DL-GP  [C402H22]  42.8 113.67 90 top
C2524  SCD1U25V2KX-1-DL-GP  [C402H22]  54.61 113.79 90 top
C2525  SC33P50V2JN-3DLGP  [C402H22]  196.42 36.17 90 top
C2526  SCD1U25V2KX-1-DL-GP  [C402H22]  102.01 149.3 0 top
C2527  SC33P50V2JN-3DLGP  [C402H22]  138.86 157.99 90 top
C2528  SC33P50V2JN-3DLGP  [C402H22]  140.59 156.97 270 top
C2529  SC10U25V5KX-DL-GP  [C805H58]  177.84 225.88 90 top
C2530  SC10U25V5KX-DL-GP  [C805H58]  177.84 223.65 90 top
C2531  SC10U25V5KX-DL-GP  [C805H58]  177.84 221.41 90 top
C2532  SC33P50V2JN-3DLGP  [C402H22]  131.57 172.21 180 top
C2533  SC33P50V2JN-3DLGP  [C402H22]  229.87 80.01 180 top
C2534  SC33P50V2JN-3DLGP  [C402H22]  228.83 80.03 0 top
CPU1  60H-6FH  [SKT-BGA1331C564462H225]  170 163 270 top
D1  AZ5325-01FDR7G-GP  [D402H24]  189.63 102.34 270 bottom
D2  BAT54A-7-F-2-GP  [SOT23-2D4-312H48]  112.68 60.82 0 bottom
D3  1SS355-4-GP  [SOD323AKH38]  119.18 62.6 0 bottom
D4  BAS40C-2-GP  [SOT-23-9H44]  181.93 20.35 180 top
D5  1SS355-4-GP  [SOD323AKH38]  11.56 168.78 270 top
D6  AZ2015-01H-GP  [SOD523AKH28]  194.61 50.93 90 bottom
D7  BAT54AW-4-GP  [SC70-2D2-312H44]  212.29 227.33 90 top
D8  P6SMB27A-1-GP  [DO214AAAK-1121H97]  23.16 126.92 0 top
D9  BAV99GP-GP  [SOT23-2D4-312H48]  97.11 68.91 0 top
D11  BAT54A-7-F-2-GP  [SOT23-2D4-312H48]  116.88 120.9 0 top
D12  AZ5325-01FDR7G-GP  [D402H24]  187.83 92.89 0 bottom
D13  BAT54A-7-F-2-GP  [SOT23-2D4-312H48]  213.11 58.17 0 bottom
D14  BAT54A-7-F-2-GP  [SOT23-2D4-312H48]  198.86 57.23 180 bottom
D15  AZ5725-01FDR7G-GP  [SOD882-10D6-1H20]  230.71 62.56 0 bottom
D16  AZ5725-01FDR7G-GP  [SOD882-10D6-1H20]  230.71 64.21 180 bottom
DCPWR1  CLX-CONN8F-1-GP-U  [CP3508P1H00-NH-U]  17.81 122 270 top
DIMM1  DDR4-260P-27-GP-U  [40-42274-26001RHF]  182 111 0 top
DIMM2  DDR4-260P-17-GP-U  [40-42261-26001RHF-U]  182 95.8 0 top
DISPC1  ACES-CON40-11-GP-U  [50398-04071-001]  82 69 90 top
DISPC2  ACES-CON40-11-GP-U  [50398-04071-001]  5 156 90 top
DMIC1  CLX-CON8-15-GP  [CI1108M1VR0-NH]  229 77.5 180 top
F2  POLYSW-1D5A6V-12-GP  [POLYSW-2114H30]  225.27 68.38 0 top
F3  POLYSW-1D1A24V-GP-U  [POLYSW-4633-UH43]  224.28 57.23 0 top
F21  POLYSW-1D1A24V-GP-U  [POLYSW-4633-UH43]  17.92 179.46 0 top
F22  POLYSW-1D5A6V-12-GP  [POLYSW-2114H30]  224.44 18.41 180 bottom
F23  POLYSW-1D5A6V-12-GP  [POLYSW-2114H30]  223.7 71.48 90 top
FANC1  BAOT-CON4-5-GP  [P254-1104S0AP-R-W]  12 176 270 top
G1  GAP-OPEN  [CON2O-U]  131.19 42.62 0 top
GPU1  R16M-E1-90-GP  [BGA1401M40H102]  70 180 0 top
H1  GEN8D5X8R5X4D5-8-F-A-GP  [GEN8D5X8R5X4D5-8-F-A]  9 231 180 top
H2  GEN315R178-8-F-A-3-GP  [GEN315R178-8-F-A-1]  229.5 229.8 180 top
H3  GEN8D5X8R5X4D5-8-F-A-GP  [GEN8D5X8R5X4D5-8-F-A]  231 5 90 top
H4  GEN315R138-8-F-A-1-GP  [GEN315R138-8-F-A-1]  82.7 5 180 top
H5  HOLE237R158-GP  [HOLE237R158]  30 230 180 top
H6  HOLE237R158-GP  [HOLE237R158]  110 230 180 top
H7  HOLE237R158-GP  [HOLE237R158]  30 130 180 top
H8  HOLE237R158-GP  [HOLE237R158]  110 130 180 top
H9  HOLE237R158-GP  [HOLE237R158]  136 189 180 top
H10  HOLE237R158-GP  [HOLE237R158]  204 189 180 top
H11  HOLE237R158-GP  [HOLE237R158]  136 137 180 top
H12  HOLE237R158-GP  [HOLE237R158]  204 137 180 top
H14  GEN315R138-8-F-A-1-GP  [GEN315R138-8-F-A-1]  5 108 180 top
H15  HOLE237R95-GP  [HOLE237R95]  106.5 68.4 180 top
H16  HOLE237R95-GP  [HOLE237R95]  106.5 18.4 180 top
HDD1  SKT-SATA7P-168-GP  [LE18077-Z55D-4F]  82 92 270 top
HDT1  SMC-CONN20A-1-GP-U2  [ASP-137098-05-1-U2]  220.83 151.61 90 top
HS1  STF256R109H99-GP  [STF256R109H99]  216.25 51 180 top
IPCC1  JWT-CON5-S18-GP  [5P1D241A4-15000D105]  17.97 106.55 180 top
JMP1  PIN-CONN6A-S3-GP  [21S-92-03GB16]  127.33 52.2 270 top
KBC1  NPCE985PB1DX-GP-U  [LQFP128H63]  110.25 53.14 90 top
L1  MHC2012S600QBP-GP  [L805H44]  133.22 149.48 180 top
L2  MHC2012S600QBP-GP  [L805H44]  160.02 56.9 0 bottom
L3  MHC2012S600QBP-GP  [L805H44]  155.7 30.23 90 bottom
L4  MHC2012S121UB-GP  [L20125H44]  137.3 43.76 0 top
L5  MHC2012S121UB-GP  [L20125H44]  139.43 43.76 0 top
L6  HCB1608KF-800T30-GP  [L603H38]  211.35 37.8 180 bottom
L7  HCB1608KF-800T30-GP  [L603H38]  198.73 35.33 90 bottom
L9  HCB1608KF-800T30-GP  [L603H38]  194.49 49.5 90 bottom
L10  BLM18SG700TN1D-GP  [L603H26]  200.58 50.16 0 bottom
L11  BLM18SG700TN1D-GP  [L603H26]  201.75 50.16 0 bottom
L12  BLM18SG700TN1D-GP  [L603H26]  205.49 52.65 90 top
L13  BLM18SG700TN1D-GP  [L603H26]  203.45 52.6 180 top
L14  BLM18SG700TN1D-GP  [L603H26]  221.74 38.73 270 bottom
L15  BLM18SG700TN1D-GP  [L603H26]  219.71 42.55 180 bottom
L16  BLM31PG391SN1L-1-GP  [L3216H52]  215.44 15.6 180 bottom
L17  BLM31PG391SN1L-1-GP  [L3216H52]  213.18 15.62 0 bottom
L18  BLM31PG391SN1L-1-GP  [L3216H52]  210.19 13.59 0 top
L19  BLM31PG391SN1L-1-GP  [L3216H52]  207.82 13.61 0 top
L20  BLM31PG391SN1L-1-GP  [L3216H52]  199.39 15.29 180 bottom
L21  BLM31PG391SN1L-1-GP  [L3216H52]  196.72 14.61 0 bottom
L22  BLM31PG391SN1L-1-GP  [L3216H52]  194.39 14.81 0 top
L23  BLM31PG391SN1L-1-GP  [L3216H52]  191.21 15.62 0 top
L24  BLM15BD102SN1D-GP  [L402H22]  92.08 60.22 270 top
L25  COIL-50OHM-GP  [L125100-4P-1H24]  106.05 83.64 180 top
L26  COIL-50OHM-GP  [L125100-4P-1H24]  104.29 85.83 180 top
L27  BLM15PX121SN1D-GP  [L402H22]  75.98 167.53 90 bottom
L28  BLM15PX121SN1D-GP  [L402H22]  98.45 149.58 180 top
L29  MHC1608S221NBP-GP  [L603H38]  186.21 18.39 270 bottom
L30  HCB1608KF-800T30-GP  [L603H38]  202.54 60.68 180 top
L31  HCB1608KF-800T30-GP  [L603H38]  216.31 59.16 90 top
L32  MHC1608S221NBP-GP  [L603H38]  186.23 17.14 270 bottom
L33  MCB1005S601FBP-GP-U  [L402H24]  196.82 37.13 270 top
L34  MCB1005S601FBP-GP-U  [L402H24]  194.11 40.59 270 top
LAUOC1  ACES-CON40-18-GP  [51540-04001-W01]  133 4 0 top
LPC1  FOX-CONN14A-S1-GP  [HL5507F]  121.16 76.33 270 top
NOREF  -  []  0 -6 0 top
NOREF#2  -  []  59.66 206.73 0 top
NOREF#3  -  []  71.88 202.18 0 top
NOREF#4  *  [unnamed#2]  88.27 156.18 0 top
NOREF#5  *  [unnamed#2]  174.35 59.28 0 top
NOREF#6  *  [unnamed#2]  8.91 7.67 0 top
NOREF#7  *  [unnamed#2]  224.87 9.58 0 top
NOREF#8  -  []  -46.56 27.74 0 top
NOREF#9  -  [unnamed#2]  230.99 217.98 0 top
NOREF#10  -  [unnamed#2]  109.1 65.2 0 top
NOREF#11  -  [unnamed#2]  3.81 224.54 0 top
NOREF#12  -  []  175.08 72.9 0 top
NOREF#13  -  []  0 0 0 top
NOREF#14  *  [unnamed#2]  144.3 128.78 0 top
NOREF#15  *  [unnamed#2]  194.18 189.61 0 top
NOREF#16  -  []  39.37 229.24 0 top
NOREF#17  -  [unnamed#2]  179.5 33 0 top
NOREF#18  *  [unnamed#2]  45.69 204.29 0 top
NOREF#19  *  [unnamed#2]  91.16 9.6 0 top
NOREF#20  *  [unnamed#2]  224.76 211.79 0 top
NOREF#21  -  []  45.48 -6 0 top
NOREF#22  -  [unnamed#2]  102.4 20 0 top
NOREF#23  *  [unnamed#2]  119.81 41.35 0 top
NOREF#24  -  [unnamed#2]  227.8 -3.09 0 top
NOREF#25  *  [unnamed#2]  100.3 65.02 0 top
NOREF#26  -  [unnamed#2]  14.44 2.72 0 top
NOREF#27  *  [unnamed#2]  16.08 227.58 0 top
NOREF#28  -  []  0 0 0 top
NOREF#29  -  [unnamed#2]  142.5 57 0 top
NOREF#30  *  [unnamed#2]  17.14 230.25 180 bottom
NOREF#31  *  [unnamed#2]  8.91 7.67 180 bottom
NOREF#32  *  [unnamed#2]  228.35 219.33 180 bottom
NOREF#33  *  [unnamed#2]  83.69 12.9 180 bottom
NOREF#34  -  []  163.92 72.93 180 bottom
NOREF#35  *  [unnamed#2]  4.57 115.82 180 bottom
NOREF#36  *  [unnamed#2]  232.54 13.59 180 bottom
OSDC1  ACES-CON10-30-GP-U  [51530-01001-W01]  4 136.5 270 top
PC1  SC22U6D3V3MX-1-DL-GP  [C603H40]  167.67 164.61 90 top
PC2  SC22U6D3V3MX-1-DL-GP  [C603H40]  167.67 164.61 270 bottom
PC3  SC22U6D3V3MX-1-DL-GP  [C603H40]  164.52 170.17 0 bottom
PC4  SC22U6D3V3MX-1-DL-GP  [C603H40]  166.59 172.8 180 bottom
PC5  SC22U6D3V3MX-1-DL-GP  [C603H40]  165.69 166.45 180 bottom
PC6  SC22U6D3V3MX-1-DL-GP  [C603H40]  165.69 163.15 180 bottom
PC7  SC22U6D3V3MX-1-DL-GP  [C603H40]  165.7 160.43 0 bottom
PC8  SC22U6D3V3MX-1-DL-GP  [C603H40]  170.36 166.43 90 top
PC9  SC22U6D3V3MX-1-DL-GP  [C603H40]  170.76 168.63 270 bottom
PC11  SC22U6D3V3MX-1-DL-GP  [C603H40]  167.69 163.16 90 top
PC12  SC22U6D3V3MX-1-DL-GP  [C603H40]  167.69 161.79 90 top
PC13  SC22U6D3V3MX-1-DL-GP  [C603H40]  167.69 161.79 270 bottom
PC14  SC22U6D3V3MX-1-DL-GP  [C603H40]  167.69 163.16 270 bottom
PC16  SC22U6D3V3MX-1-DL-GP  [C603H40]  167.67 165.93 270 bottom
PC17  SC22U6D3V3MX-1-DL-GP  [C603H40]  167.67 167.23 270 bottom
PC18  SC22U6D3V3MX-1-DL-GP  [C603H40]  166.58 170.1 0 bottom
PC19  SC22U6D3V3MX-1-DL-GP  [C603H40]  170.76 167.37 270 bottom
PC20  SC22U6D3V3MX-1-DL-GP  [C603H40]  167.67 167.23 90 top
PC21  SC22U6D3V3MX-1-DL-GP  [C603H40]  167.67 165.93 90 top
PC22  SC22U6D3V3MX-1-DL-GP  [C603H40]  170.37 166.1 270 bottom
PC23  SC22U6D3V3MX-1-DL-GP  [C603H40]  170.87 164.84 270 bottom
PC24  SC22U6D3V3MX-1-DL-GP  [C603H40]  165.7 160.43 180 top
PC25  SC22U6D3V3MX-1-DL-GP  [C603H40]  165.69 163.15 0 top
PC26  SC22U6D3V3MX-1-DL-GP  [C603H40]  165.69 166.45 0 top
PC27  SC22U6D3V3MX-1-DL-GP  [C603H40]  170.76 164.95 90 top
PC28  SC22U6D3V3MX-1-DL-GP  [C603H40]  176.44 165.43 180 bottom
PC29  SC22U6D3V3MX-1-DL-GP  [C603H40]  174.65 170.36 0 bottom
PC30  SC22U6D3V3MX-1-DL-GP  [C603H40]  176.64 159.38 0 bottom
PC31  SC22U6D3V3MX-1-DL-GP  [C603H40]  176.68 162.16 180 bottom
PC32  SC22U6D3V3MX-1-DL-GP  [C603H40]  173.53 167.25 270 top
PC33  SC22U6D3V3MX-1-DL-GP  [C603H40]  173.53 165.83 270 top
PC34  SC22U6D3V3MX-1-DL-GP  [C603H40]  173.93 168.31 90 bottom
PC35  SC22U6D3V3MX-1-DL-GP  [C603H40]  170.79 163.62 270 top
PC36  SC22U6D3V3MX-1-DL-GP  [C603H40]  173.51 164.36 270 top
PC37  SC22U6D3V3MX-1-DL-GP  [C603H40]  173.51 162.83 270 top
PC38  SC22U6D3V3MX-1-DL-GP  [C603H40]  173.51 161.28 270 top
PC39  SC22U6D3V3MX-1-DL-GP  [C603H40]  170.38 162.32 270 top
PC40  SC22U6D3V3MX-1-DL-GP  [C603H40]  176.45 170.16 0 bottom
PC41  SC22U6D3V3MX-1-DL-GP  [C603H40]  173.68 167 90 bottom
PC42  SC22U6D3V3MX-1-DL-GP  [C603H40]  173.69 165.68 90 bottom
PC44  SC22U6D3V3MX-1-DL-GP  [C603H40]  173.66 164.21 90 bottom
PC45  SC22U6D3V3MX-1-DL-GP  [C603H40]  173.66 162.78 90 bottom
PC46  SC22U6D3V3MX-1-DL-GP  [C603H40]  173.66 161.34 90 bottom
PC47  SC22U6D3V3MX-1-DL-GP  [C603H40]  170.87 163.58 90 bottom
PC48  SC22U6D3V3MX-1-DL-GP  [C603H40]  170.91 160.63 90 bottom
PC49  SC22U6D3V3MX-1-DL-GP  [C603H40]  170.4 162.31 90 bottom
PC50  SC22U6D3V3MX-1-DL-GP  [C603H40]  173.55 159.59 270 top
PC51  SC22U6D3V3MX-1-DL-GP  [C603H40]  170.75 159.4 270 top
PC52  SC22U6D3V3MX-1-DL-GP  [C603H40]  167.68 159.41 90 top
PC53  SC22U6D3V3MX-1-DL-GP  [C603H40]  170.75 160.68 270 top
PC54  SC22U6D3V3MX-1-DL-GP  [C603H40]  170.89 157.65 90 bottom
PC55  SC22U6D3V3MX-1-DL-GP  [C603H40]  167.97 156.37 270 bottom
PC56  SC22U6D3V3MX-1-DL-GP  [C603H40]  167.97 157.66 270 bottom
PC57  SC22U6D3V3MX-1-DL-GP  [C603H40]  173.61 157.64 90 bottom
PC58  SC22U6D3V3MX-1-DL-GP  [C603H40]  170.92 159.36 90 bottom
PC59  SC22U6D3V3MX-1-DL-GP  [C603H40]  173.7 159.64 90 bottom
PC60  SC22U6D3V3MX-1-DL-GP  [C603H40]  167.68 159.41 270 bottom
PC61  SC22U6D3V3MX-1-DL-GP  [C603H40]  161.42 144.58 90 bottom
PC62  SC10U6D3V3MX-DL-GP  [C603H36]  139.5 161.17 90 bottom
PC63  SC22U6D3V3MX-1-DL-GP  [C603H40]  156.01 166.17 0 bottom
PC64  SC22U6D3V3MX-1-DL-GP  [C603H40]  157.33 166.14 0 bottom
PC65  SC10U6D3V3MX-DL-GP  [C603H36]  145.52 159.64 90 bottom
PC66  SC10U6D3V3MX-DL-GP  [C603H36]  159.41 161.19 180 bottom
PC67  SC22P50V2JN-4DLGP  [C402H22]  105.28 41.73 180 top
PC87  SCD1U50V3KX-DL-GP  [C603H35]  21.94 135.28 90 bottom
PC88  SCD1U50V3KX-DL-GP  [C603H35]  21.94 136.5 90 bottom
PC92  SCD1U25V2KX-1-DL-GP  [C402H22]  21.01 112.65 90 top
PC94  SCD1U25V2KX-1-DL-GP  [C402H22]  112.01 16.76 0 bottom
PC95  SC10U25V5KX-DL-GP  [C805H58]  114.17 17.17 180 top
PC96  SC10U25V5KX-DL-GP  [C805H58]  110.92 11.02 180 bottom
PC97  SCD1U50V3KX-DL-GP  [C603H35]  106.68 28.7 0 top
PC98  SC10U25V5KX-DL-GP  [C805H58]  107.01 28.83 180 bottom
PC99  SC10U25V5KX-DL-GP  [C805H58]  108.64 35.03 180 bottom
PC100  SC10U25V5KX-DL-GP  [C805H58]  108.89 35.08 0 top
PC101  SC10U25V5KX-DL-GP  [C805H58]  110.87 35.05 0 top
PC102  SC10U25V5KX-DL-GP  [C805H58]  110.62 35.03 180 bottom
PC103  SCD1U25V2KX-1-DL-GP  [C402H22]  112.06 35.26 180 bottom
PC104  SCD1U50V3KX-DL-GP  [C603H35]  103.71 25.4 180 top
PC105  SCD1U50V3KX-DL-GP  [C603H35]  104.42 36.63 0 top
PC106  SC10U10V5KX-2DLGP  [C805H50]  133.68 23.34 0 bottom
PC107  SC10U10V5KX-2DLGP  [C805H50]  131.65 23.34 0 bottom
PC108  SC1500P50V2KX-2-DL-GP  [C402H22]  114 18.29 90 bottom
PC109  SC1500P50V2KX-2-DL-GP  [C402H22]  114.38 34.01 90 bottom
PC110  SC10U10V5KX-2DLGP  [C805H50]  134.54 32.21 180 bottom
PC111  SC10U10V5KX-2DLGP  [C805H50]  132.51 32.23 180 bottom
PC112  SC4D7U25V5KX-DL-GP  [C805H54]  97.54 29.84 0 top
PC113  SC4D7U25V5KX-DL-GP  [C805H54]  106.93 31.88 180 top
PC114  SC680P50V2KX-2DLGP  [C402H22]  213.21 229.41 270 bottom
PC115  SC150P50V2JN-3DLGP  [C402H22]  215.62 227.58 0 bottom
PC116  SC470P50V2KX-3DLGP  [C402H22]  217.58 228.65 180 bottom
PC117  SC68P50V2JN-1DLGP  [C402H22]  216.43 226.14 270 bottom
PC118  SCD022U16V2KX-3DLGP  [C402H22]  219.55 227.47 90 top
PC119  SC330P50V2KX-3-LL-GP  [C402H22]  216.64 223.22 0 top
PC120  SCD22U10V2KX-2-GP  [C402H22]  218.07 227.07 180 top
PC121  SC220P50V2KX-3-LL-GP  [C402H22]  219.71 225.43 90 bottom
PC122  SCD1U25V2KX-1-DL-GP  [C402H22]  219.53 225.43 270 top
PC123  SCD22U10V2KX-2-GP  [C402H22]  222.17 227.5 0 bottom
PC124  SCD22U10V2KX-2-GP  [C402H22]  221.16 224.46 90 top
PC125  SCD22U25V3KX-DL-GP  [C603H36]  211.3 221.64 270 top
PC126  SCD1U25V2KX-1-DL-GP  [C402H22]  217.25 220.75 270 top
PC127  SCD1U25V2KX-1-DL-GP  [C402H22]  223.72 218.97 90 top
PC128  SC1U10V2KX-1DLGP  [C402H22]  207.85 217.58 270 top
PC129  SC1U10V2KX-1DLGP  [C402H22]  211.4 220.5 90 top
PC130  SCD1U25V2KX-1-DL-GP  [C402H22]  217.3 216.66 270 top
PC131  SC10P50V2JN-4DLGP  [C402H22]  206.68 211.1 270 top
PC132  SC470P50V2KX-3DLGP  [C402H22]  213.89 211.61 270 bottom
PC133  SC68P50V2JN-1DLGP  [C402H22]  206.32 213.79 270 top
PC134  SC150P50V2JN-3DLGP  [C402H22]  207.62 212.12 90 top
PC135  SCD22U25V3KX-DL-GP  [C603H36]  220.14 212.75 0 bottom
PC137  SCD22U25V3KX-DL-GP  [C603H36]  217.78 212.75 0 bottom
PC138  SC1KP50V2KX-1DLGP  [C402H22]  209.93 211.53 270 top
PC139  SCD022U16V2KX-3DLGP  [C402H22]  216.46 212.83 0 top
PC140  SCD22U10V2KX-2-GP  [C402H22]  216.74 212.65 180 bottom
PC141  SCD01U50V2KX-1DLGP  [C402H22]  215.01 216.43 180 top
PC142  SC330P50V2KX-3-LL-GP  [C402H22]  215.9 216.46 180 top
PC143  SCD1U25V2KX-1-DL-GP  [C402H22]  219.68 213.41 90 top
PC144  SC820P50V2KX-1-LL-GP  [C402H22]  214.96 211.3 90 top
PC145  SCD1U25V2KX-1-DL-GP  [C402H22]  194.84 222.43 270 bottom
PC146  SC10U25V5KX-DL-GP  [C805H58]  194.51 220.8 270 bottom
PC147  SC10U25V5KX-DL-GP  [C805H58]  187.32 221.44 270 top
PC148  SC10U25V5KX-DL-GP  [C805H58]  187.32 221.18 90 bottom
PC149  SCD1U50V3KX-DL-GP  [C603H35]  207.21 211.94 180 bottom
PC150  SC1500P50V2KX-2-DL-GP  [C402H22]  195.4 218.34 180 top
PC151  SCD1U25V2KX-1-DL-GP  [C402H22]  178.41 222.4 270 bottom
PC152  SC10U25V5KX-DL-GP  [C805H58]  178.28 220.98 270 bottom
PC153  SC10U25V5KX-DL-GP  [C805H58]  171.42 223.98 270 top
PC154  SC10U25V5KX-DL-GP  [C805H58]  171.42 220.93 90 bottom
PC155  SCD1U50V3KX-DL-GP  [C603H35]  203.68 223.62 270 bottom
PC156  SC1500P50V2KX-2-DL-GP  [C402H22]  178.94 218.34 180 top
PC157  SCD1U25V2KX-1-DL-GP  [C402H22]  162.31 223.47 270 bottom
PC158  SC10U25V5KX-DL-GP  [C805H58]  156.36 226.54 90 bottom
PC159  SC10U25V5KX-DL-GP  [C805H58]  162.28 221.84 270 bottom
PC160  SC10U25V5KX-DL-GP  [C805H58]  156.36 226.54 270 top
PC161  SCD1U50V3KX-DL-GP  [C603H35]  209.93 229.95 270 bottom
PC162  SC1500P50V2KX-2-DL-GP  [C402H22]  162.61 218.21 180 top
PC163  SC10U25V5KX-DL-GP  [C805H58]  219.86 193.88 270 bottom
PC164  SC10U25V5KX-DL-GP  [C805H58]  219.86 195.81 270 bottom
PC165  SC10U25V5KX-DL-GP  [C805H58]  215.8 198.04 90 bottom
PC166  SCD1U25V2KX-1-DL-GP  [C402H22]  219.81 191.92 90 top
PC167  SC10U25V5KX-DL-GP  [C805H58]  219.91 191.87 270 bottom
PC168  SC10U25V5KX-DL-GP  [C805H58]  219.84 197.74 270 bottom
PC169  SC1U10V2KX-1DLGP  [C402H22]  212.67 205.82 180 top
PC170  SCD1U50V3KX-DL-GP  [C603H35]  215.29 199.82 270 top
PC171  SC1500P50V2KX-2-DL-GP  [C402H22]  215.26 188.85 90 top
PC172  SC10U25V5KX-DL-GP  [C805H58]  228.7 200.13 270 bottom
PC173  SC10U25V5KX-DL-GP  [C805H58]  223.95 199.54 90 bottom
PC174  SC10U25V5KX-DL-GP  [C805H58]  228.7 200.1 90 top
PC175  SC10U25V5KX-DL-GP  [C805H58]  229.26 198.17 270 bottom
PC176  SCD1U50V3KX-DL-GP  [C603H35]  224.05 206.45 0 top
PC177  SC1U10V2KX-1DLGP  [C402H22]  221.18 201.02 0 top
PC178  SC1500P50V2KX-2-DL-GP  [C402H22]  223.72 189.31 270 top
PC179  SC1U10V2KX-1DLGP  [C402H22]  219.58 141.1 270 top
PC180  SC10U25V5KX-DL-GP  [C805H58]  225.55 131.19 270 top
PC181  SC10U25V5KX-DL-GP  [C805H58]  225.58 130.96 90 bottom
PC182  SCD1U25V2KX-1-DL-GP  [C402H22]  225.5 132.59 270 top
PC183  SC10U25V5KX-DL-GP  [C805H58]  225.55 129.16 270 top
PC184  SC10U25V5KX-DL-GP  [C805H58]  225.58 129.03 90 bottom
PC185  SC10U25V5KX-DL-GP  [C805H58]  228.47 131.7 0 bottom
PC186  SC1U10V2KX-1DLGP  [C402H22]  218.14 138.81 0 top
PC187  SCD1U50V3KX-DL-GP  [C603H35]  221.34 135.59 180 top
PC188  SC10U6D3V3MX-DL-GP  [C603H36]  225.43 134.39 0 top
PC189  SC22U6D3V5MX-2DLGP  [C805H54]  225.13 97.29 180 bottom
PC190  SC22U6D3V5MX-2DLGP  [C805H54]  228.85 106.51 270 bottom
PC191  SC1500P50V2KX-2-DL-GP  [C402H22]  223.9 125.35 180 top
PC192  SC18P50V2JN-1DLGP  [C402H22]  226.78 144.03 270 top
PC193  SC10U6D3V3MX-DL-GP  [C603H36]  228.08 140.33 180 top
PC194  SC10U6D3V3MX-DL-GP  [C603H36]  229.32 140.33 180 top
PC195  SCD047U25V2KX-4-GP  [C402H22]  228.7 142.93 90 top
PC196  SCD1U25V2KX-1-DL-GP  [C402H22]  223.9 143.13 270 top
PC208  SC4D7U25V5KX-DL-GP  [C805H54]  146.25 211.61 90 bottom
PC209  SCD1U25V2KX-1-DL-GP  [C402H22]  151.89 212.85 270 top
PC210  SC22U6D3V5MX-2DLGP  [C805H54]  153.67 199.77 90 top
PC211  SC22U6D3V5MX-2DLGP  [C805H54]  153.67 201.93 90 top
PC212  SC22U6D3V5MX-2DLGP  [C805H54]  153.67 201.8 270 bottom
PC213  SC22U6D3V5MX-2DLGP  [C805H54]  153.67 199.77 270 bottom
PC214  SC22U6D3V5MX-2DLGP  [C805H54]  145.92 201.8 90 bottom
PC215  SC22U6D3V5MX-2DLGP  [C805H54]  145.92 201.8 270 top
PC216  SCD1U25V2KX-1-DL-GP  [C402H22]  152.65 219.07 270 bottom
PC217  SC10U25V5KX-DL-GP  [C805H58]  153.16 222.53 90 top
PC218  SC10U25V5KX-DL-GP  [C805H58]  153.16 220.6 90 top
PC219  SC22U6D3V5MX-2DLGP  [C805H54]  145.92 199.77 90 bottom
PC220  SC220P50V2KX-3GP  [C402H22]  144.4 217.7 180 bottom
PC221  SCD01U50V2KX-1DLGP  [C402H22]  146.51 213.06 90 bottom
PC222  SC2D2U10V3KX-1DLGP-U  [C603H36]  149.74 22.27 180 top
PC223  SCD1U25V2KX-1-DL-GP  [C402H22]  143.44 19.63 90 top
PC224  SC22U6D3V5MX-2DLGP  [C805H54]  143.09 31.39 90 bottom
PC225  SC22U6D3V5MX-2DLGP  [C805H54]  148.09 31.28 270 bottom
PC226  SC22U6D3V5MX-2DLGP  [C805H54]  148.04 31.28 90 top
PC227  SC22U6D3V5MX-2DLGP  [C805H54]  143.14 31.34 270 top
PC228  SCD1U25V2KX-1-DL-GP  [C402H22]  142.93 17.02 270 top
PC229  SC10U25V5KX-DL-GP  [C805H58]  142.69 15.55 270 top
PC230  SC10U25V5KX-DL-GP  [C805H58]  145.64 12.32 90 top
PC231  SC470P50V2KX-3DLGP  [C402H22]  150.82 19.13 270 top
PC232  SC1U10V2KX-1DLGP  [C402H22]  147.47 18.03 90 bottom
PC233  SCD1U25V2KX-1-DL-GP  [C402H22]  130.25 112.62 180 top
PC234  SC2D2U10V3KX-1DLGP-U  [C603H36]  139.65 112.55 90 top
PC235  SC22U6D3V5MX-2DLGP  [C805H54]  131.34 121.01 90 bottom
PC236  SC22U6D3V5MX-2DLGP  [C805H54]  138.05 121.01 270 bottom
PC237  SC22U6D3V5MX-2DLGP  [C805H54]  131.34 121.01 270 top
PC238  SC22U6D3V5MX-2DLGP  [C805H54]  138.05 121.01 90 top
PC239  SCD1U25V2KX-1-DL-GP  [C402H22]  131.57 105.16 0 top
PC240  SC10U25V5KX-DL-GP  [C805H58]  130.18 104.78 0 top
PC241  SC10U25V5KX-DL-GP  [C805H58]  130.18 104.78 180 bottom
PC242  SC470P50V2KX-3DLGP  [C402H22]  140.34 108.84 180 top
PC243  SC1U10V2KX-1DLGP  [C402H22]  139.67 110.46 90 top
PC244  SC1U10V2KX-1DLGP  [C402H22]  9.3 201.73 90 bottom
PC245  SCD01U50V2KX-1DLGP  [C402H22]  9.86 202.62 90 top
PC246  SCD1U50V3KX-DL-GP  [C603H35]  15.85 195.73 0 top
PC247  SC10U25V5KX-DL-GP  [C805H58]  14.33 184.89 90 top
PC248  SC10U25V5KX-DL-GP  [C805H58]  7.66 184.63 270 top
PC249  SC10U25V5KX-DL-GP  [C805H58]  14.31 186.9 90 top
PC250  SC10U25V5KX-DL-GP  [C805H58]  7.68 186.61 270 top
PC251  SC10U25V5KX-DL-GP  [C805H58]  15.01 201.84 90 top
PC252  SC10U25V5KX-DL-GP  [C805H58]  15.01 201.85 270 bottom
PC253  SC1U50V3KX-1-GP  [C603H36]  10.19 202.82 90 bottom
PC254  SC1500P50V2KX-2-DL-GP  [C402H22]  14.45 198.35 90 top
PC255  SC1KP50V2KX-1DLGP  [C402H22]  7.04 200 270 bottom
PC257  SC10U6D3V3MX-DL-GP  [C603H36]  134.95 66.22 0 top
